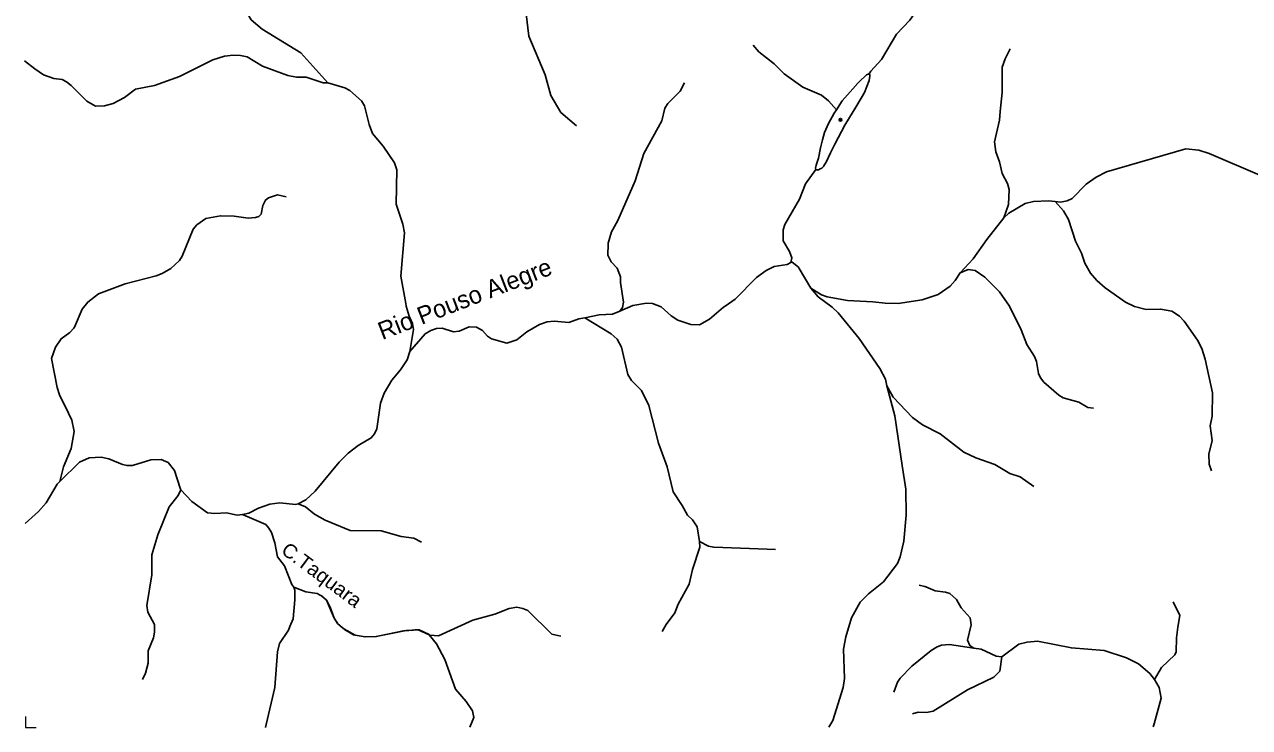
# Model space of a CAD drawing. Extents: x 473.9 to 500, y 7733.1 to 7760.8.
# Drawn here: x 473.93 to 480.86, y 7733.14 to 7737.12 of the extents above; entities that cross this region are included whole.
import ezdxf
from ezdxf.enums import TextEntityAlignment as Align

# ---------------------------------------------------------------- set-up
doc = ezdxf.new("R2010")
doc.units = 0
doc.header["$LTSCALE"] = 0.032
doc.header["$PDMODE"] = 32
doc.header["$PDSIZE"] = 0.016
for name, color, linetype, lineweight in [('2', 7, 'Continuous', 25), ('63', 7, 'Continuous', 13), ('7', 7, 'Continuous', 25)]:
    doc.layers.add(name, color=color, linetype=linetype, lineweight=lineweight)
doc.layers.add('61', color=7, linetype='Continuous')

msp = doc.modelspace()

# ---------------------------------------------------------------- linework, layer by layer
at = {"layer": '2'}
for points in [[(478.7077, 7736.8415), (478.7112, 7736.8363), (478.7112, 7736.8276), (478.7068, 7736.8042), (478.6817, 7736.7358), (478.6376, 7736.6622), (478.5691, 7736.5505), (478.5128, 7736.444), (478.4886, 7736.3937), (478.4652, 7736.3461), (478.4514, 7736.3201), (478.4479, 7736.3166), (478.4384, 7736.308), (478.4306, 7736.3028), (478.421, 7736.2985), (478.4167, 7736.2976), (478.4158, 7736.2976), (478.4115, 7736.2976), (478.4055, 7736.3)], [(478.5215, 7736.638), (478.5553, 7736.689), (478.615, 7736.7575), (478.6428, 7736.7886), (478.6627, 7736.8086), (478.68, 7736.8242), (478.693, 7736.8354), (478.7025, 7736.8406), (478.706, 7736.8415), (478.7077, 7736.8415)], [(478.4055, 7736.3), (478.4029, 7736.3071), (478.4063, 7736.3236), (478.4202, 7736.3634), (478.4314, 7736.4232), (478.4375, 7736.4457), (478.4436, 7736.4673), (478.4488, 7736.4881), (478.4548, 7736.5098), (478.4765, 7736.5609), (478.5094, 7736.6198), (478.5215, 7736.638)]]:
    msp.add_lwpolyline(points, dxfattribs=at)
msp.add_point((478.5449, 7736.5808), dxfattribs=at)
at = {"layer": '63'}
msp.add_lwpolyline([(473.9307, 7733.2009), (473.9307, 7733.1393), (473.9914, 7733.1393)], dxfattribs=at)
at = {"layer": '7'}
for p, q in [((475.5177, 7733.9085), (475.4507, 7733.9342)), ((475.5825, 7733.8978), (475.5177, 7733.9085)), ((475.5947, 7733.8917), (475.5825, 7733.8978)), ((475.6776, 7733.7583), (475.6352, 7733.8605)), ((475.7324, 7733.6979), (475.7117, 7733.716)), ((475.7968, 7733.6627), (475.7324, 7733.6979)), ((475.8313, 7733.6565), (475.7968, 7733.6627)), ((475.8546, 7733.6526), (475.8313, 7733.6565)), ((475.917, 7733.6541), (475.8546, 7733.6526)), ((475.9347, 7733.6577), (475.917, 7733.6541)), ((476.0771, 7733.6868), (475.9347, 7733.6577)), ((476.1008, 7733.6895), (476.0771, 7733.6868))]:
    msp.add_line(p, q, dxfattribs=at)
for points in [[(477.0495, 7736.5475), (476.9609, 7736.6233), (476.9045, 7736.7197), (476.8729, 7736.8359), (476.7804, 7737.0548), (476.7661, 7737.1823), (476.7491, 7737.2341), (476.7253, 7737.2692), (476.6653, 7737.3299), (476.6007, 7737.3834), (476.5315, 7737.4575), (476.467, 7737.5501), (476.4067, 7737.7331), (476.3689, 7737.8078), (476.2859, 7737.933), (476.2697, 7737.9963)], [(479.1304, 7737.5072), (479.1134, 7737.4801), (479.0472, 7737.406), (479.0245, 7737.3573), (479.0023, 7737.2715), (479.0022, 7737.2713), (478.9762, 7737.203), (478.938, 7737.1459), (478.8628, 7737.0668), (478.7764, 7736.9225), (478.7165, 7736.8575), (478.7077, 7736.8415)], [(475.1175, 7737.3864), (475.143, 7737.3643), (475.1598, 7737.3342), (475.1727, 7737.2579), (475.1844, 7737.1887), (475.2078, 7737.1481), (475.2713, 7737.0952), (475.4901, 7736.9601), (475.6424, 7736.7907)], [(478.05, 7737.0042), (478.0826, 7736.9672), (478.1689, 7736.8983), (478.2263, 7736.842), (478.3314, 7736.7661), (478.4369, 7736.7209), (478.4772, 7736.6879), (478.5215, 7736.638)], [(479.5059, 7736.9838), (479.4765, 7736.927), (479.46, 7736.8797), (479.4607, 7736.7367), (479.4498, 7736.629), (479.4448, 7736.5802), (479.4159, 7736.4568), (479.424, 7736.3999), (479.4455, 7736.3439), (479.46, 7736.2768), (479.4903, 7736.2209), (479.4993, 7736.1863), (479.4969, 7736.1023), (479.4701, 7736.0258)], [(473.9254, 7736.9153), (473.9833, 7736.8709), (474.0338, 7736.8363), (474.0916, 7736.815), (474.139, 7736.8092), (474.1632, 7736.7965), (474.189, 7736.775), (474.2783, 7736.6871), (474.327, 7736.6577), (474.3789, 7736.6601), (474.427, 7736.6731), (474.491, 7736.7085), (474.5545, 7736.7553), (474.6608, 7736.7748), (474.8035, 7736.827), (474.9922, 7736.9213), (475.0569, 7736.9415), (475.1068, 7736.9479), (475.148, 7736.9462), (475.1852, 7736.9373), (475.2728, 7736.8847), (475.4171, 7736.8317), (475.4649, 7736.8229), (475.5191, 7736.8227), (475.6159, 7736.7916), (475.6424, 7736.7907)], [(475.6424, 7736.7907), (475.7397, 7736.7619), (475.7675, 7736.747), (475.8337, 7736.6887), (475.8503, 7736.66), (475.8761, 7736.5539), (475.8952, 7736.5047), (475.9565, 7736.4317), (476.0206, 7736.3371), (476.034, 7736.2973), (476.0299, 7736.1036), (476.0675, 7735.9901), (476.0764, 7735.9407), (476.0565, 7735.6948), (476.0835, 7735.5411), (476.0861, 7735.5264), (476.1025, 7735.4693), (476.1228, 7735.4279), (476.1278, 7735.3928), (476.1061, 7735.269)], [(477.6626, 7736.7899), (477.6372, 7736.7436), (477.5674, 7736.6741), (477.5503, 7736.6475), (477.5328, 7736.5756), (477.4321, 7736.3904), (477.3824, 7736.2349), (477.285, 7736.0112), (477.2568, 7735.9599), (477.2493, 7735.9462), (477.2303, 7735.8829), (477.2301, 7735.8774), (477.2278, 7735.8153), (477.2461, 7735.7769), (477.2807, 7735.7405), (477.2991, 7735.6918), (477.299, 7735.6604), (477.3169, 7735.5492), (477.3099, 7735.5182), (477.2959, 7735.4973)], [(481.2199, 7736.2289), (481.165, 7736.2178), (481.0453, 7736.2284), (480.9323, 7736.263), (480.6313, 7736.3904), (480.5739, 7736.4095), (480.5007, 7736.4163), (480.0508, 7736.286), (479.9923, 7736.2559), (479.9357, 7736.217), (479.8557, 7736.1355), (479.8278, 7736.1215), (479.7898, 7736.1148), (479.7604, 7736.1182)], [(478.4055, 7736.3), (478.3464, 7736.219), (478.312, 7736.1327), (478.2299, 7735.9878), (478.2204, 7735.959), (478.2205, 7735.8955), (478.2561, 7735.835), (478.2686, 7735.8001), (478.2636, 7735.7739)], [(475.4077, 7736.1445), (475.3572, 7736.1566), (475.3061, 7736.1385), (475.2904, 7736.1264), (475.2746, 7736.0953), (475.265, 7736.0476), (475.2527, 7736.0339), (475.2333, 7736.0275), (475.1919, 7736.0243), (475.1133, 7736.0362), (475.0346, 7736.0379), (474.9526, 7736.0227), (474.9016, 7735.9863), (474.8804, 7735.9612), (474.8175, 7735.8083), (474.8026, 7735.7848), (474.754, 7735.74), (474.7041, 7735.7101), (474.6714, 7735.6978), (474.4956, 7735.6523), (474.3436, 7735.5963), (474.2832, 7735.5491), (474.2512, 7735.5094), (474.2089, 7735.4069), (474.2042, 7735.4018), (474.1816, 7735.377), (474.1329, 7735.341), (474.1016, 7735.2936), (474.0785, 7735.2286), (474.1094, 7735.0645), (474.1236, 7735.0238), (474.1743, 7734.919), (474.1928, 7734.8807), (474.2075, 7734.8165), (474.1904, 7734.7191), (474.1456, 7734.6152), (474.1259, 7734.5319)], [(479.7604, 7736.1182), (479.722, 7736.1227), (479.6383, 7736.1189), (479.5901, 7736.1069), (479.4979, 7736.0519), (479.4701, 7736.0258)], [(480.646, 7734.5922), (480.633, 7734.6302), (480.6306, 7734.687), (480.6498, 7734.7647), (480.6371, 7734.8474), (480.6482, 7734.9022), (480.6514, 7735.0343), (480.6098, 7735.2261), (480.5908, 7735.2852), (480.5664, 7735.3339), (480.4914, 7735.441), (480.4641, 7735.4691), (480.4208, 7735.4973), (480.3569, 7735.5094), (480.2756, 7735.5063), (480.2101, 7735.5239), (480.159, 7735.5485), (480.0431, 7735.6302), (479.9968, 7735.671), (479.9602, 7735.7134), (479.9289, 7735.7687), (479.9088, 7735.8265), (479.8751, 7735.8942), (479.8351, 7736.0173), (479.8081, 7736.0649), (479.7604, 7736.1182)], [(479.4701, 7736.0258), (479.3729, 7735.9026), (479.2961, 7735.7933), (479.2217, 7735.7155)], [(478.2636, 7735.7739), (478.2437, 7735.7622), (478.1702, 7735.7504), (478.1236, 7735.7287), (478.0695, 7735.688), (477.9481, 7735.5651), (477.8928, 7735.5267), (477.8826, 7735.5196), (477.8025, 7735.4531), (477.7474, 7735.4205), (477.6973, 7735.4214), (477.6233, 7735.4473), (477.5869, 7735.4714), (477.5301, 7735.5215), (477.4809, 7735.5408), (477.4472, 7735.5431), (477.37, 7735.5291), (477.2959, 7735.4973)], [(478.3776, 7735.627), (478.3108, 7735.7396), (478.3064, 7735.7471), (478.271, 7735.7747), (478.2636, 7735.7739)], [(478.3776, 7735.627), (478.438, 7735.5907), (478.4695, 7735.5788), (478.584, 7735.5583), (478.7287, 7735.5511), (478.7979, 7735.5419), (478.8718, 7735.5416), (479.0065, 7735.5625), (479.0986, 7735.5918), (479.1651, 7735.6395), (479.1945, 7735.6716), (479.2217, 7735.7155)], [(479.9764, 7734.9485), (479.9456, 7734.9526), (479.8946, 7734.9821), (479.805, 7735.0074), (479.7802, 7735.0224), (479.6968, 7735.0955), (479.6765, 7735.12), (479.6667, 7735.1449), (479.6555, 7735.2127), (479.6438, 7735.2403), (479.6007, 7735.3085), (479.5678, 7735.391), (479.5016, 7735.5263), (479.4457, 7735.6079), (479.3619, 7735.6909), (479.3068, 7735.7276), (479.2679, 7735.7331), (479.2217, 7735.7155)], [(478.8078, 7735.0748), (478.7999, 7735.1123), (478.7668, 7735.1729), (478.6507, 7735.3422), (478.5313, 7735.4881), (478.4973, 7735.5205), (478.4186, 7735.5789), (478.3776, 7735.627)], [(477.2959, 7735.4973), (477.2551, 7735.4798), (477.1778, 7735.4766), (477.098, 7735.459)], [(477.098, 7735.459), (477.0627, 7735.4541), (477.0078, 7735.4341), (476.9247, 7735.4406), (476.8839, 7735.4371), (476.8406, 7735.4226), (476.7695, 7735.3798), (476.7127, 7735.3346), (476.6557, 7735.3155), (476.5698, 7735.341), (476.5471, 7735.3565), (476.5185, 7735.3888), (476.4848, 7735.4067), (476.4428, 7735.4084), (476.3867, 7735.3839), (476.3546, 7735.3813), (476.2897, 7735.4004), (476.2576, 7735.3988), (476.2253, 7735.3875), (476.194, 7735.3682), (476.1061, 7735.269)], [(477.7461, 7734.1935), (477.7344, 7734.2758), (477.7069, 7734.3159), (477.6788, 7734.3413), (477.6487, 7734.3974), (477.5969, 7734.4738), (477.5646, 7734.6152), (477.5139, 7734.7505), (477.4604, 7734.9631), (477.4177, 7735.0475), (477.3623, 7735.1057), (477.3418, 7735.138), (477.3047, 7735.2941), (477.2797, 7735.339), (477.2468, 7735.3693), (477.098, 7735.459)], [(476.1061, 7735.269), (476.0909, 7735.2216), (476.0533, 7735.1651), (476.0041, 7735.1059), (475.9617, 7735.0337), (475.9417, 7734.9763), (475.9207, 7734.8312), (475.9076, 7734.8025), (475.8881, 7734.7791), (475.8145, 7734.7361), (475.7571, 7734.693), (475.7066, 7734.6425), (475.5703, 7734.4774), (475.5179, 7734.4281), (475.4742, 7734.4071)], [(478.4784, 7733.142), (478.4843, 7733.1514), (478.5011, 7733.1783), (478.5604, 7733.3666), (478.5669, 7733.4168), (478.5612, 7733.5832), (478.575, 7733.6524), (478.6071, 7733.7599), (478.6564, 7733.8488), (478.7034, 7733.8958), (478.7884, 7733.9648), (478.8675, 7734.0682), (478.8831, 7734.1067), (478.9035, 7734.1953), (478.9164, 7734.3423), (478.9147, 7734.4891), (478.8945, 7734.6231), (478.8523, 7734.9038), (478.8078, 7735.0748)], [(479.6393, 7734.5041), (479.5613, 7734.56), (479.5035, 7734.5785), (479.4193, 7734.6294), (479.312, 7734.6666), (479.2438, 7734.6987), (479.109, 7734.8033), (479.0089, 7734.8538), (478.9525, 7734.8944), (478.8431, 7735.0111), (478.8078, 7735.0748)], [(474.8105, 7734.4856), (474.8072, 7734.4954), (474.7739, 7734.5956), (474.7385, 7734.6409), (474.699, 7734.658), (474.6415, 7734.6548), (474.5361, 7734.6229), (474.5062, 7734.6228), (474.4804, 7734.6284), (474.4036, 7734.6613), (474.3594, 7734.67), (474.2917, 7734.666), (474.2366, 7734.6421), (474.1259, 7734.5319)], [(474.1259, 7734.5319), (474.1112, 7734.5172), (474.049, 7734.4128), (474.0044, 7734.3627), (473.9293, 7734.2948)], [(474.5934, 7733.4106), (474.6099, 7733.4463), (474.6253, 7733.5032), (474.6251, 7733.5742), (474.655, 7733.6472), (474.6621, 7733.6787), (474.6606, 7733.7236), (474.624, 7733.7922), (474.6172, 7733.8302), (474.647, 7734.0048), (474.6462, 7734.1173), (474.6801, 7734.23), (474.744, 7734.3894), (474.7956, 7734.4533), (474.8084, 7734.4811), (474.8105, 7734.4856)], [(475.1587, 7734.3458), (475.1291, 7734.3424), (475.0694, 7734.3549), (475.0034, 7734.351), (474.9623, 7734.3558), (474.8727, 7734.4193), (474.8105, 7734.4856)], [(475.4742, 7734.4071), (475.4596, 7734.4023), (475.3701, 7734.4111), (475.3151, 7734.4047), (475.2497, 7734.3823), (475.1952, 7734.3536), (475.1587, 7734.3458)], [(476.1738, 7734.1896), (476.129, 7734.2115), (476.0582, 7734.2208), (475.9449, 7734.2531), (475.7688, 7734.2547), (475.6277, 7734.3131), (475.5673, 7734.3469), (475.5156, 7734.39), (475.4742, 7734.4071)], [(475.4507, 7733.9342), (475.438, 7733.9496), (475.397, 7734.0549), (475.3579, 7734.1058), (475.3419, 7734.1848), (475.3238, 7734.2447), (475.3095, 7734.2682), (475.2914, 7734.2891), (475.1587, 7734.3458)], [(477.5355, 7733.6837), (477.5576, 7733.7232), (477.6078, 7733.7889), (477.6265, 7733.8382), (477.6878, 7733.951), (477.7064, 7734.0346), (477.7489, 7734.1604), (477.7461, 7734.1935)], [(478.1772, 7734.1475), (478.1294, 7734.1493), (477.827, 7734.1607), (477.7969, 7734.1667), (477.7461, 7734.1935)], [(475.289, 7733.1395), (475.293, 7733.1563), (475.3429, 7733.3666), (475.3581, 7733.5673), (475.3695, 7733.6151), (475.4192, 7733.6905), (475.4279, 7733.7111), (475.4462, 7733.7544), (475.4558, 7733.8628), (475.4558, 7733.9163), (475.4507, 7733.9342)], [(475.5825, 7733.8978), (475.5822, 7733.898), (475.5177, 7733.9085)], [(478.9899, 7733.9448), (479.0227, 7733.9376), (479.0286, 7733.9363), (479.0806, 7733.913), (479.1397, 7733.9067), (479.164, 7733.8978), (479.2008, 7733.8645), (479.2287, 7733.818), (479.2799, 7733.7598), (479.2844, 7733.7208), (479.2642, 7733.6337), (479.2766, 7733.6035), (479.2998, 7733.5881)], [(475.5947, 7733.8917), (475.5828, 7733.8978), (475.5825, 7733.8978)], [(475.6352, 7733.8605), (475.6101, 7733.884), (475.5947, 7733.8917)], [(475.6352, 7733.8605), (475.6071, 7733.8854), (475.5947, 7733.8917)], [(475.6776, 7733.7583), (475.6558, 7733.8211), (475.6352, 7733.8605)], [(480.4289, 7733.851), (480.4654, 7733.7736), (480.4553, 7733.7068), (480.4465, 7733.6481), (480.4462, 7733.567), (480.4382, 7733.5516), (480.3621, 7733.4787), (480.3231, 7733.4105)], [(476.9608, 7733.6566), (476.9104, 7733.6687), (476.774, 7733.8017), (476.7468, 7733.8142), (476.7127, 7733.8202), (476.6696, 7733.8126), (476.589, 7733.7812), (476.4639, 7733.7469), (476.2694, 7733.6595), (476.2202, 7733.6629), (476.2165, 7733.6645)], [(475.7117, 7733.716), (475.6972, 7733.7295), (475.6776, 7733.7583)], [(475.7117, 7733.716), (475.6978, 7733.7282), (475.6776, 7733.7583)], [(475.7324, 7733.6979), (475.7295, 7733.6995), (475.7117, 7733.716)], [(475.7968, 7733.6627), (475.7882, 7733.6642), (475.7371, 7733.6938), (475.7324, 7733.6979)], [(476.2165, 7733.6645), (476.216, 7733.6652), (476.1592, 7733.6925), (476.1355, 7733.6934), (476.1008, 7733.6895)], [(476.2165, 7733.6645), (476.1534, 7733.6926), (476.1008, 7733.6895)], [(475.8313, 7733.6565), (475.7982, 7733.6619), (475.7968, 7733.6627)], [(475.8546, 7733.6526), (475.8528, 7733.6526), (475.8313, 7733.6565)], [(475.917, 7733.6541), (475.9166, 7733.654), (475.8548, 7733.6526), (475.8546, 7733.6526)], [(475.9347, 7733.6577), (475.9174, 7733.6541), (475.917, 7733.6541)], [(476.0771, 7733.6868), (476.0716, 7733.6862), (475.9347, 7733.6577)], [(476.1008, 7733.6895), (476.0858, 7733.6886), (476.0771, 7733.6868)], [(476.4473, 7733.1404), (476.4693, 7733.196), (476.4622, 7733.2347), (476.4262, 7733.2859), (476.3647, 7733.3568), (476.3051, 7733.5247), (476.2572, 7733.613), (476.2165, 7733.6645)], [(479.4584, 7733.5397), (479.5546, 7733.6107), (479.6011, 7733.6229), (479.6607, 7733.6277), (479.8522, 7733.5901), (480.0372, 7733.5764), (480.1642, 7733.5346), (480.2313, 7733.4994), (480.2956, 7733.4455), (480.3231, 7733.4105)], [(478.8462, 7733.3396), (478.8669, 7733.3958), (478.8827, 7733.4192), (478.9482, 7733.4864), (479.0578, 7733.576), (479.0917, 7733.5969), (479.1171, 7733.6053), (479.1616, 7733.6093), (479.2998, 7733.5881)], [(479.2998, 7733.5881), (479.3408, 7733.5825), (479.4257, 7733.543), (479.4584, 7733.5397)], [(478.9526, 7733.216), (478.985, 7733.226), (479.0328, 7733.2245), (479.0693, 7733.2319), (479.2641, 7733.3534), (479.4137, 7733.425), (479.4464, 7733.4575), (479.4584, 7733.5397)], [(480.3231, 7733.4105), (480.3482, 7733.365), (480.3604, 7733.306), (480.3204, 7733.1603), (480.3158, 7733.1434)]]:
    msp.add_lwpolyline(points, dxfattribs=at)

# ---------------------------------------------------------------- texts
at = {"layer": '61'}
msp.add_text('Rio Pouso Alegre', height=0.1, rotation=21.14, dxfattribs=at).set_placement((476.4361, 7735.521), align=Align.CENTER)
at = {"layer": '61', "width": 1.05}
msp.add_text('C.Taquara', height=0.08, rotation=323.31, dxfattribs=at).set_placement((475.5847, 7733.972), align=Align.CENTER)

doc.saveas('drawing.dxf')
